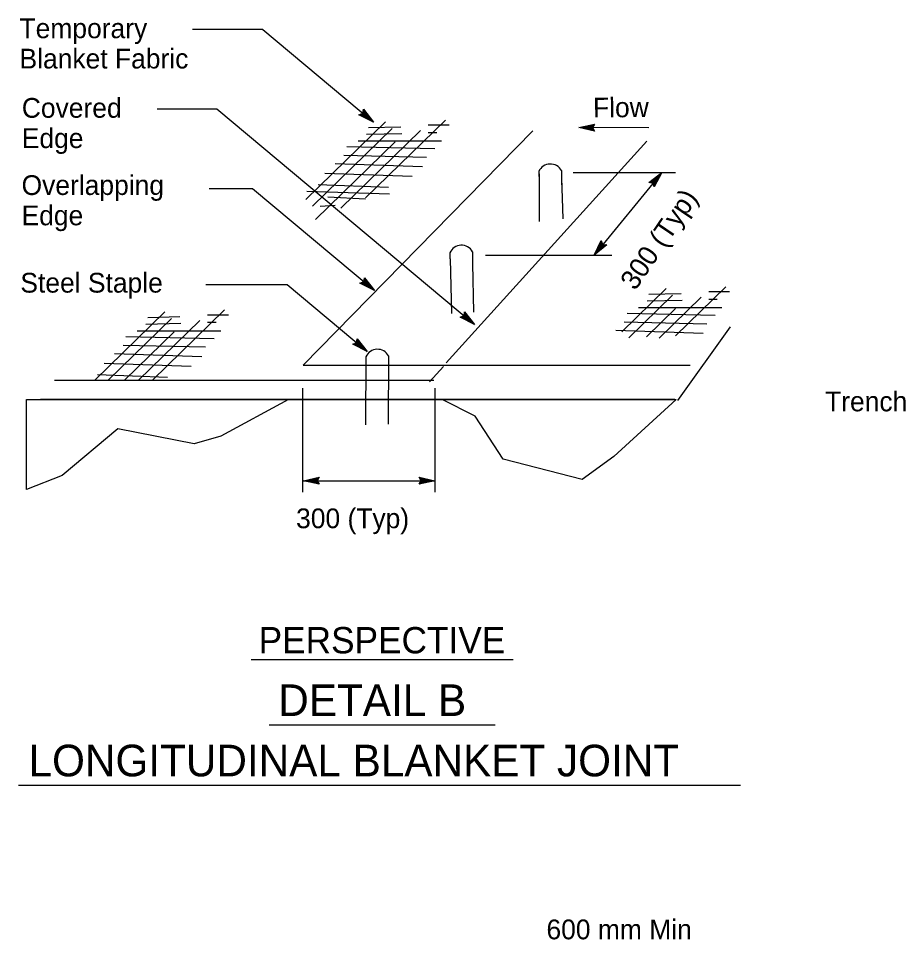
# Model space of a CAD drawing. Extents: x 6712486 to 6713732, y 1869200 to 1869925.
# Drawn here: x 6712746.5 to 6713027, y 1869623.4 to 1869914.6 of the extents above; entities that cross this region are included whole.
import ezdxf

# ---------------------------------------------------------------- set-up
doc = ezdxf.new("R2010")
doc.units = 0
for name, color, linetype in [('56 Stg 3 Anno', 7, 'Continuous'), ('57 Undefined', 7, 'Continuous'), ('60 Nongeo Data', 7, 'Continuous')]:
    doc.layers.add(name, color=color, linetype=linetype)

msp = doc.modelspace()

# ---------------------------------------------------------------- linework, layer by layer
at = {"layer": '56 Stg 3 Anno'}
for p, q in [((6712855.41, 1869884.54), (6712855.62, 1869885.83)), ((6712855.56, 1869885.48), (6712857.86, 1869882.51)), ((6712855.62, 1869885.83), (6712855.62, 1869885.83)), ((6712855.62, 1869885.83), (6712858.74, 1869881.77)), ((6712854.19, 1869884.12), (6712855.41, 1869884.54)), ((6712858.74, 1869881.77), (6712854.19, 1869884.12)), ((6712854.19, 1869884.12), (6712854.19, 1869884.12)), ((6712857.85, 1869882.51), (6712854.53, 1869884.22)), ((6712856.97, 1869883.25), (6712854.83, 1869884.35)), ((6712856.09, 1869883.98), (6712855.17, 1869884.46)), ((6712855.45, 1869884.81), (6712856.09, 1869883.98)), ((6712855.52, 1869885.13), (6712856.97, 1869883.25)), ((6712858.74, 1869881.77), (6712858.74, 1869881.77)), ((6712923.65, 1869880.08), (6712928.64, 1869881.19)), ((6712928.64, 1869878.97), (6712923.65, 1869880.08)), ((6712923.65, 1869880.08), (6712923.65, 1869880.08)), ((6712928.46, 1869879.26), (6712924.8, 1869880.08)), ((6712924.81, 1869880.08), (6712928.45, 1869880.89)), ((6712925.95, 1869880.08), (6712928.3, 1869880.6)), ((6712928.27, 1869879.56), (6712925.95, 1869880.08)), ((6712927.1, 1869880.08), (6712928.1, 1869880.3)), ((6712928.12, 1869879.85), (6712927.1, 1869880.08)), ((6712928.64, 1869881.19), (6712927.98, 1869880.08)), ((6712927.98, 1869880.08), (6712928.64, 1869878.97)), ((6712928.64, 1869881.19), (6712928.64, 1869881.19)), ((6712928.64, 1869878.97), (6712928.64, 1869878.97)), ((6712945.85, 1869862.74), (6712949.9, 1869865.88)), ((6712949.9, 1869865.88), (6712947.56, 1869861.32)), ((6712949.9, 1869865.88), (6712949.9, 1869865.88)), ((6712947.14, 1869862.54), (6712945.85, 1869862.74)), ((6712945.85, 1869862.74), (6712945.85, 1869862.74)), ((6712946.2, 1869862.69), (6712949.17, 1869864.99)), ((6712946.55, 1869862.65), (6712948.43, 1869864.11)), ((6712946.87, 1869862.58), (6712947.7, 1869863.22)), ((6712947.56, 1869861.33), (6712947.14, 1869862.54)), ((6712947.7, 1869863.22), (6712947.22, 1869862.31)), ((6712948.43, 1869864.11), (6712947.33, 1869861.96)), ((6712949.16, 1869864.98), (6712947.46, 1869861.67)), ((6712947.56, 1869861.33), (6712947.56, 1869861.33)), ((6712928.52, 1869839.73), (6712930.77, 1869844.33)), ((6712932.51, 1869842.95), (6712928.52, 1869839.73)), ((6712929.24, 1869840.64), (6712930.88, 1869843.99)), ((6712932.16, 1869842.99), (6712929.24, 1869840.63)), ((6712929.96, 1869841.53), (6712931.01, 1869843.7)), ((6712931.81, 1869843.03), (6712929.96, 1869841.53)), ((6712930.67, 1869842.43), (6712931.13, 1869843.36)), ((6712931.49, 1869843.09), (6712930.67, 1869842.43)), ((6712930.77, 1869844.33), (6712930.77, 1869844.33)), ((6712930.77, 1869844.33), (6712931.22, 1869843.12)), ((6712931.22, 1869843.12), (6712932.51, 1869842.95)), ((6712932.51, 1869842.95), (6712932.51, 1869842.95)), ((6712928.52, 1869839.73), (6712928.52, 1869839.73)), ((6712854.52, 1869830.89), (6712855.74, 1869831.32)), ((6712859.07, 1869828.55), (6712854.52, 1869830.89)), ((6712854.52, 1869830.89), (6712854.52, 1869830.89)), ((6712858.18, 1869829.29), (6712854.86, 1869831)), ((6712857.3, 1869830.02), (6712855.16, 1869831.12)), ((6712856.42, 1869830.76), (6712855.5, 1869831.23)), ((6712855.74, 1869831.32), (6712855.94, 1869832.6)), ((6712855.78, 1869831.59), (6712856.42, 1869830.76)), ((6712855.85, 1869831.9), (6712857.3, 1869830.02)), ((6712855.89, 1869832.26), (6712858.18, 1869829.28)), ((6712855.94, 1869832.6), (6712855.94, 1869832.6)), ((6712855.94, 1869832.6), (6712859.07, 1869828.55)), ((6712859.07, 1869828.55), (6712859.07, 1869828.55)), ((6712887.4, 1869820.54), (6712887.6, 1869821.83)), ((6712887.55, 1869821.48), (6712889.84, 1869818.51)), ((6712887.6, 1869821.83), (6712887.6, 1869821.83)), ((6712887.6, 1869821.83), (6712890.72, 1869817.77)), ((6712886.18, 1869820.12), (6712887.4, 1869820.54)), ((6712890.72, 1869817.77), (6712886.18, 1869820.12)), ((6712886.18, 1869820.12), (6712886.18, 1869820.12)), ((6712889.83, 1869818.51), (6712886.52, 1869820.22)), ((6712888.96, 1869819.24), (6712886.81, 1869820.35)), ((6712888.07, 1869819.98), (6712887.16, 1869820.45)), ((6712887.43, 1869820.81), (6712888.07, 1869819.98)), ((6712887.5, 1869821.13), (6712888.96, 1869819.24)), ((6712890.72, 1869817.77), (6712890.72, 1869817.77)), ((6712853.46, 1869812.05), (6712853.66, 1869813.33)), ((6712853.61, 1869812.99), (6712855.9, 1869810.02)), ((6712853.66, 1869813.33), (6712853.66, 1869813.33)), ((6712853.66, 1869813.33), (6712856.78, 1869809.28)), ((6712856.78, 1869809.28), (6712852.23, 1869811.63)), ((6712852.24, 1869811.63), (6712853.46, 1869812.05)), ((6712852.24, 1869811.63), (6712852.24, 1869811.63)), ((6712855.89, 1869810.02), (6712852.58, 1869811.73)), ((6712855.02, 1869810.75), (6712852.87, 1869811.86)), ((6712854.13, 1869811.49), (6712853.22, 1869811.96)), ((6712853.49, 1869812.32), (6712854.13, 1869811.49)), ((6712853.56, 1869812.64), (6712855.02, 1869810.75)), ((6712856.78, 1869809.28), (6712856.78, 1869809.28)), ((6712836.62, 1869768.43), (6712841.62, 1869769.53)), ((6712837.78, 1869768.43), (6712841.43, 1869769.23)), ((6712841.62, 1869769.53), (6712840.95, 1869768.43)), ((6712841.62, 1869769.53), (6712841.62, 1869769.53)), ((6712873.9, 1869768.43), (6712873.23, 1869769.54)), ((6712873.23, 1869769.54), (6712873.23, 1869769.54)), ((6712873.23, 1869769.54), (6712878.23, 1869768.43)), ((6712873.41, 1869769.25), (6712877.08, 1869768.43)), ((6712841.62, 1869767.31), (6712836.62, 1869768.43)), ((6712836.62, 1869768.43), (6712836.62, 1869768.43)), ((6712841.44, 1869767.61), (6712837.77, 1869768.43)), ((6712838.93, 1869768.42), (6712841.28, 1869768.95)), ((6712841.25, 1869767.91), (6712838.93, 1869768.42)), ((6712840.08, 1869768.42), (6712841.08, 1869768.65)), ((6712841.1, 1869768.19), (6712840.08, 1869768.42)), ((6712840.95, 1869768.43), (6712841.62, 1869767.31)), ((6712841.62, 1869767.31), (6712841.62, 1869767.31)), ((6712878.23, 1869768.43), (6712873.23, 1869767.32)), ((6712873.23, 1869767.32), (6712873.9, 1869768.43)), ((6712873.23, 1869767.32), (6712873.23, 1869767.32)), ((6712877.07, 1869768.42), (6712873.43, 1869767.62)), ((6712875.93, 1869768.43), (6712873.58, 1869767.91)), ((6712873.61, 1869768.95), (6712875.93, 1869768.43)), ((6712873.76, 1869768.66), (6712874.78, 1869768.43)), ((6712874.78, 1869768.43), (6712873.77, 1869768.21)), ((6712878.23, 1869768.43), (6712878.23, 1869768.43))]:
    msp.add_line(p, q, dxfattribs=at)
at = {"layer": '57 Undefined'}
for p, q in [((6712820.12, 1869711.94), (6712902.91, 1869711.94)), ((6712825.81, 1869691.29), (6712897.28, 1869691.29)), ((6712746.54, 1869672.22), (6712974.81, 1869672.22))]:
    msp.add_line(p, q, dxfattribs=at)
at = {"layer": '60 Nongeo Data'}
for p, q in [((6712862.61, 1869881.84), (6712837.41, 1869857.29)), ((6712864.7, 1869879.74), (6712839.51, 1869855.19)), ((6712881.5, 1869882.43), (6712856.31, 1869857.89)), ((6712857.21, 1869880.04), (6712867.4, 1869880.34)), ((6712876.1, 1869880.94), (6712882.7, 1869880.94)), ((6712836.58, 1869804.96), (6712909.13, 1869879.02)), ((6712873.7, 1869879.14), (6712848.51, 1869854.59)), ((6712856.61, 1869877.94), (6712867.7, 1869878.24)), ((6712876.1, 1869878.54), (6712878.8, 1869878.54)), ((6712865.6, 1869875.55), (6712840.41, 1869851)), ((6712850.31, 1869874.05), (6712878.2, 1869873.45)), ((6712853.91, 1869875.85), (6712880.3, 1869875.85)), ((6712881.72, 1869805.75), (6712945.18, 1869875.78)), ((6712849.41, 1869871.36), (6712875.5, 1869870.76)), ((6712846.71, 1869868.66), (6712874.3, 1869867.77)), ((6712843.38, 1869865.62), (6712870.98, 1869864.72)), ((6712911.14, 1869866.23), (6712911.06, 1869866.18)), ((6712911.13, 1869864.65), (6712911.14, 1869866.23)), ((6712911.14, 1869865.44), (6712911.13, 1869850.4)), ((6712918.22, 1869866.48), (6712918.19, 1869861.98)), ((6712918.22, 1869866.48), (6712918.22, 1869866.48)), ((6712921.95, 1869865.88), (6712954.3, 1869865.88)), ((6712949.9, 1869865.88), (6712928.52, 1869839.73)), ((6712918.21, 1869864.23), (6712918.67, 1869851.24)), ((6712837.71, 1869859.98), (6712863.81, 1869859.08)), ((6712841.31, 1869862.08), (6712863.51, 1869861.18)), ((6712844.31, 1869858.19), (6712856.31, 1869857.59)), ((6712841.91, 1869855.19), (6712846.71, 1869855.49)), ((6712883, 1869840.55), (6712882.92, 1869840.51)), ((6712882.99, 1869838.53), (6712883, 1869840.55)), ((6712890.09, 1869840.8), (6712890.06, 1869837.15)), ((6712890.09, 1869840.8), (6712890.09, 1869840.8)), ((6712894.21, 1869839.73), (6712934.18, 1869839.73)), ((6712882.99, 1869838.53), (6712883.46, 1869821.33)), ((6712890.06, 1869837.15), (6712890.38, 1869821.74)), ((6712951.26, 1869829.15), (6712937.26, 1869815.52)), ((6712945.86, 1869827.36), (6712956.06, 1869827.66)), ((6712970.15, 1869829.75), (6712954.24, 1869814.25)), ((6712964.76, 1869828.26), (6712971.35, 1869828.26)), ((6712953.36, 1869827.06), (6712939.51, 1869813.57)), ((6712945.26, 1869825.26), (6712956.36, 1869825.56)), ((6712962.36, 1869826.46), (6712949.07, 1869813.52)), ((6712964.76, 1869825.86), (6712967.45, 1869825.86)), ((6712792.82, 1869821.82), (6712770.72, 1869800.28)), ((6712811.72, 1869822.41), (6712788.9, 1869800.18)), ((6712942.56, 1869823.17), (6712968.95, 1869823.17)), ((6712954.26, 1869822.87), (6712945.08, 1869813.93)), ((6712794.92, 1869819.72), (6712774.95, 1869800.26)), ((6712803.92, 1869819.12), (6712784.5, 1869800.2)), ((6712787.42, 1869820.02), (6712797.62, 1869820.32)), ((6712806.32, 1869820.92), (6712812.92, 1869820.92)), ((6712806.32, 1869818.52), (6712809.02, 1869818.52)), ((6712938.06, 1869818.68), (6712964.15, 1869818.08)), ((6712938.96, 1869821.37), (6712966.85, 1869820.77)), ((6712784.12, 1869815.83), (6712810.52, 1869815.83)), ((6712786.82, 1869817.92), (6712797.92, 1869818.22)), ((6712935.36, 1869815.98), (6712962.96, 1869815.09)), ((6712954.99, 1869793.83), (6712971.69, 1869817.06)), ((6712795.82, 1869815.53), (6712780.12, 1869800.23)), ((6712780.53, 1869814.03), (6712808.42, 1869813.43)), ((6712779.63, 1869811.34), (6712805.72, 1869810.74)), ((6712776.93, 1869808.64), (6712804.52, 1869807.75)), ((6712856.33, 1869786.09), (6712856.48, 1869807.66)), ((6712863.56, 1869807.91), (6712863.41, 1869786.35)), ((6712773.6, 1869805.6), (6712801.2, 1869804.7)), ((6712836.58, 1869804.96), (6712958.89, 1869804.96)), ((6712876.5, 1869799.73), (6712880.92, 1869804.55)), ((6712771.53, 1869802.06), (6712793.72, 1869801.16)), ((6712757.92, 1869800.22), (6712877.91, 1869800.22)), ((6712836.35, 1869797.66), (6712836.35, 1869764.87)), ((6712878.23, 1869797.66), (6712878.23, 1869764.87)), ((6712753.5, 1869794.12), (6712954.48, 1869794.12)), ((6712836.62, 1869768.43), (6712878.23, 1869768.43))]:
    msp.add_line(p, q, dxfattribs=at)
for points in [[(6712823.79, 1869911.03), (6712801.59, 1869911.09)], [(6712823.79, 1869911.03), (6712858.74, 1869881.77)], [(6712790.42, 1869885.98), (6712809.26, 1869885.98)], [(6712809.26, 1869885.98), (6712890.72, 1869817.77)], [(6712945.85, 1869880.02), (6712923.65, 1869880.08)], [(6712806.79, 1869860.83), (6712820.51, 1869860.83)], [(6712820.51, 1869860.83), (6712859.07, 1869828.55)], [(6712805.76, 1869830.47), (6712831.48, 1869830.47)], [(6712831.48, 1869830.47), (6712856.78, 1869809.28)]]:
    msp.add_lwpolyline(points, dxfattribs=at)
for points in [[(6712831.88, 1869794.12), (6712810.58, 1869782.48), (6712802.14, 1869780.08), (6712778.02, 1869784.89), (6712760.34, 1869770.05), (6712749.08, 1869765.63), (6712749.08, 1869794.12), (6712834.29, 1869794.12)], [(6712753.5, 1869794.12), (6712954.48, 1869794.12), (6712934.78, 1869776.06), (6712924.73, 1869768.84), (6712899.81, 1869775.26), (6712890.97, 1869788.9), (6712880.52, 1869794.12), (6712868.86, 1869794.12), (6712954.08, 1869794.12)]]:
    msp.add_lwpolyline(points, close=True, dxfattribs=at)
for centre in [(6712914.71, 1869864.54), (6712886.58, 1869838.87), (6712860.05, 1869805.98)]:
    msp.add_arc(centre, 4.01, 28.8752, 155.8761, dxfattribs=at)

# ---------------------------------------------------------------- texts
at = {"layer": '57 Undefined'}
for s, height, p in [('PERSPECTIVE', 8.3268, (6712822.48, 1869713.87)), ('DETAIL B', 9.992, (6712828.69, 1869694.08)), ('LONGITUDINAL BLANKET JOINT', 9.9921, (6712749.74, 1869675.01))]:
    msp.add_text(s, height=height, dxfattribs=at).set_placement(p)
at = {"layer": '60 Nongeo Data'}
for s, height, p in [('Temporary ', 6.245, (6712746.89, 1869908.32)), ('Blanket Fabric', 6.2451, (6712746.89, 1869898.74)), ('Covered ', 6.245, (6712747.61, 1869883.17)), ('Edge', 6.245, (6712747.61, 1869873.59)), ('Overlapping ', 6.2451, (6712747.54, 1869858.76)), ('Edge', 6.245, (6712747.54, 1869849.18)), ('Steel Staple', 6.2451, (6712747.16, 1869827.9)), ('Trench', 6.245, (6713001.54, 1869790.38)), ('300 (Typ)', 6.245, (6712834.32, 1869753.43)), ('600 mm Min', 6.245, (6712913.47, 1869623.5))]:
    msp.add_text(s, height=height, dxfattribs=at).set_placement(p)
for s, rotation, p in [('Flow', 0.4741, (6712928.2, 1869883.25)), ('300 (Typ)', 55.848, (6712941.54, 1869828.28))]:
    msp.add_text(s, height=6.245, rotation=rotation, dxfattribs=at).set_placement(p)

doc.saveas('drawing.dxf')
